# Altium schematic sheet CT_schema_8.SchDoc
size 274 x 160 mm
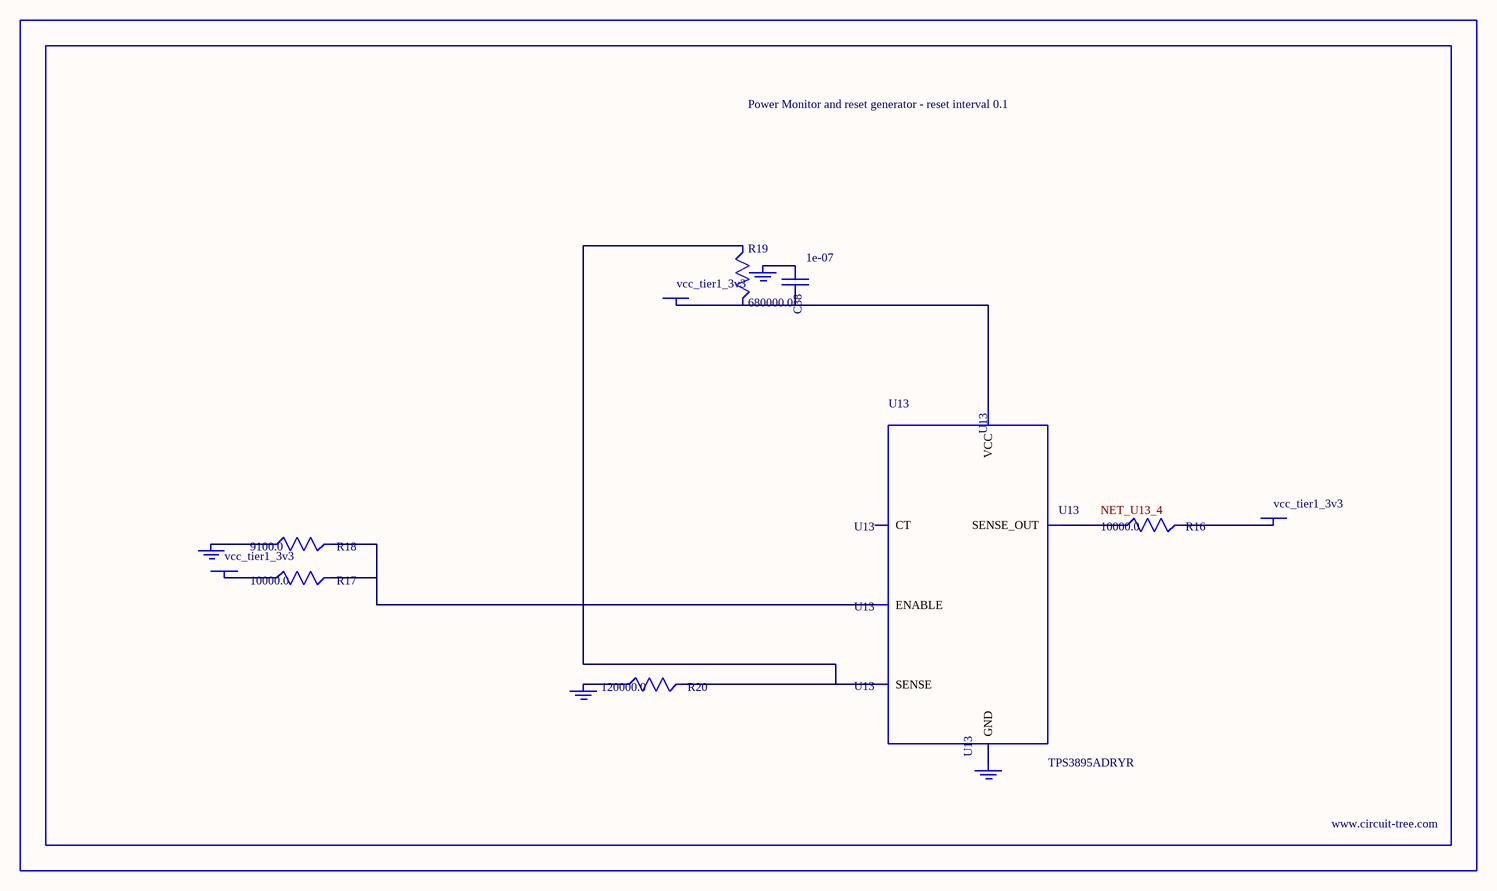
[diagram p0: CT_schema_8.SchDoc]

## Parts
BORDER7  (no value)
C38  1e-07  [C0402]
GND_INSTANCE_7_0  (no value)
GND_INSTANCE_7_1  (no value)
GND_INSTANCE_7_2  (no value)
GND_INSTANCE_7_3  (no value)
POWER_INSTANCE_7_0  vcc_tier1_3v3
POWER_INSTANCE_7_1  vcc_tier1_3v3
POWER_INSTANCE_7_2  vcc_tier1_3v3
R16  10000.0  [R0603]
R17  10000.0  [R0603]
R18  9100.0  [R0603]
R19  680000.0  [R0603]
R20  120000.0  [R0603]
U13  TPS3895ADRYR  [SON-6]

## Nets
NetC38_1: C38.1 GND_INSTANCE_7_2.0(GND)
NetC38_2: C38.2 POWER_INSTANCE_7_2.0(PWR) R19.2 U13.6(VCC)
NetGND_INSTANCE_7_0_0: GND_INSTANCE_7_0.0(GND) R18.1
NetGND_INSTANCE_7_1_0: GND_INSTANCE_7_1.0(GND) R20.1
NetGND_INSTANCE_7_3_0: GND_INSTANCE_7_3.0(GND) U13.2(GND)
NetPOWER_INSTANCE_7_0_0: POWER_INSTANCE_7_0.0(PWR) R17.1
NetPOWER_INSTANCE_7_1_0: POWER_INSTANCE_7_1.0(PWR) R16.2
NetR16_1: R16.1 U13.4(SENSE_OUT)
NetR17_2: R17.2 R18.2 U13.1(ENABLE)
NetR19_1: R19.1 R20.2 U13.3(SENSE)

Not connected (* = marked no-connect by the designer): U13 5(CT)

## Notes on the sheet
- Labels drawn without touching a wire or pin: NET_U13_4

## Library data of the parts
BORDER7 = BORDER_PAGE7
C38 = C0402C104K3RACTU
GND_INSTANCE_7_0-GND_INSTANCE_7_3 = GND
POWER_INSTANCE_7_0-POWER_INSTANCE_7_2 = PWR
R16 R17 = RC0603JR-0710KL
R18 = RC0603JR-079K1L
R19 = RC0603JR-07680KL
R20 = RC0603JR-07120KL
